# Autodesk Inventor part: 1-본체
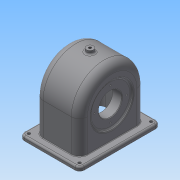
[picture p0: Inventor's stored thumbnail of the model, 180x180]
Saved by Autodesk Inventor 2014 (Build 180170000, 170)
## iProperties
Created: 2016-01
Part Number: 1-본체
Material: Generic
Document SubType Name: Modeling
Designer: Administrator
Density: 1 g/cm^3
Appearance: Default
Author: Administrator
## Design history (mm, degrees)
sketch "스케치1"
  geometry: L1 (-44, -70)-(44, -70); L2 (52, -62)-(52, 62); L3 (44, 70)-(-44, 70); L4 (-52, 62)-(-52, -62); L5 (-52, -70)-(52, 70); L6 (52, -70)-(-52, 70); A1 r 8 centre (-44, 62) between (-44, 70) and (-52, 62); A2 r 8 centre (44, 62) between (52, 62) and (44, 70); A3 r 8 centre (-44, -62) between (-52, -62) and (-44, -70); A4 r 8 centre (44, -62) between (44, -70) and (52, -62); 1 further point
  constraints: 12 end point, 8 point on circle, 8 point on line, 8 tangent, 4 centre point, 3 equal radius, 2 midpoint, 2 parallel, 1 horizontal, 1 perpendicular
  dimensions: "d0" = 104 distance of L5.end L6.end; "d1" = 140 distance of L6.start L5.end; "d2" = 8 radius of A1
extrude "돌출1" new body sketch "스케치1" distance "d3" = 7; taper "d4" = 0 deg
node "작업 평면1"
sketch "스케치3"
  geometry: L1 (-7, 124)-(-7, 0) reference; L2 (-64, 11)-(-7, 11); L3 (-64, 113)-(-7, 113); L4 (-64, 5)-(-7, 5); L5 (-64, 119)-(-7, 119); L6 (-7, 5)-(-7, 119); A1 r 57 centre (-64, 62) between (-64, 119) and (-64, 5); A2 r 51 centre (-64, 62) between (-64, 113) and (-64, 11); 1 further point
  constraints: 10 end point, 4 perpendicular, 4 point on circle, 4 point on line, 4 tangent, 2 centre point, 1 coincident, 1 collinear
  dimensions: "d6" = 57 radius of A1; "d7" = 64 distance of point (0, 62) A1.centre; "d8" = 0 vertical distance of A1.centre point (0, 62); "d12" = 102 diameter of A2
extrude "돌출3" join sketch "스케치3" stored distance "d15" = 77; taper "d16" = 0 deg
extrude "돌출4" cut sketch "스케치3" stored distance "d17" = 67; taper "d18" = 0 deg
node "작업 평면3"
sketch "스케치5"
  geometry: L1 (-38.5, 57)-(-38.5, -57) reference; L2 (38.5, -57)-(38.5, 57) reference; L3 (0, 0)-(67.019, 0); L4 (48.5, 0)-(48.5, 31); L5 (48.5, 31)-(38.5, 31); L6 (38.5, 31)-(38.5, 0)
  constraints: 8 end point, 3 perpendicular, 3 point on line, 1 midpoint
  dimensions: "d20" = 62 diameter of L5 L3; "d21" = 10 distance between parallel lines of L4 L2
revolve "회전1" sketch "스케치5" stored, may be unused: angle "d22" = 90 deg
sketch "스케치6"
  geometry: L1 (48.5, -31)-(48.5, 31) reference; L2 (-33.5, 51)-(-33.5, -51) reference; L3 (38.5, 57)-(-38.5, 57) reference; L4 (0, 0)-(-44.74, 0); L5 (-33.5, 39.747)-(-19.5, 28); L6 (-19.5, 28)-(-19.5, 0); L7 (-33.5, 39.747)-(-33.5, 0); L8 (-38.5, 57)-(-38.5, -57) reference; 1 further point
  constraints: 8 end point, 3 point on line, 1 coincident, 1 midpoint, 1 parallel, 1 perpendicular
  dimensions: "d26" = 33.5 distance from line of point (0, 0) L2 (derived); "d27" = 56 diameter of L5.end L4; "d28" = 50 deg angle of L6 L5; "d30" = 19 distance between parallel lines of L8 L6
revolve "회전2" sketch "스케치6" stored, may be unused: angle "d31" = 90 deg
sketch "스케치7"
  geometry: L1 (0, 0)-(57.526, 0); L2 (33.5, -51)-(33.5, 51) reference; L3 (33.5, 20)-(43.5, 20); L4 (33.5, 20)-(33.5, 0); L5 (-33.5, 39.747)-(-19.5, 28) reference; L6 (-19.5, -28)-(-19.5, 28) reference; L7 (0, 0)-(-45.884, 0); L8 (-19.5, 20)-(-35.5, 20); L9 (-35.5, 20)-(-35.5, 34.899); L10 (-38.5, 57)-(-38.5, -57) reference; L11 (-35.5, 34.899)-(-38.5, 37.416); L12 (-38.5, 37.416)-(-38.5, 0); L13 (-19.5, 20)-(-19.5, 0); L14 (-19.5, 0)-(-38.5, 0); L15 (33.5, 0)-(43.5, 0); L16 (48.5, -31)-(48.5, 31) reference; L17 (43.5, 20)-(48.5, 20); L18 (48.5, 20)-(48.5, 0); L19 (48.5, 0)-(43.5, 0)
  constraints: 28 end point, 6 point on line, 4 midpoint, 4 perpendicular, 3 collinear, 2 parallel, 1 horizontal
  dimensions: "d32" = 40 diameter of L3 L1; "d34" = 5 distance between parallel lines of L11 L5; "d35" = 40 diameter of L8 L7; "d36" = 3 distance between parallel lines of L9 L10
revolve "회전3" sketch "스케치7" stored, may be unused: angle "d37" = 90 deg
node "작업 평면4"
sketch "스케치8"
  geometry: C1 r 6 at (0, 0); 1 further point
  constraints: 1 centre point, 1 coincident
  dimensions: "d39" = 12 diameter of C1
extrude "돌출5" join sketch "스케치8" stored distance "d40" = 67; taper "d41" = 0 deg
hole "구멍1" diameter "d44" = 4.459; stored, may be unused: countersink angle "d48" = 90 deg, drill point angle "d50" = 118 deg; dims "d42" = 10, "d43" = 10, "d45" = 6, "d46" = 4, "d47" = 2, "d49" = 8
sketch "스케치9"
  geometry: C1 r 20 at (0, 0) reference; C2 r 31 at (0, 0) reference; A1 r 24 centre (0, 0) between (0, 24) and (-24, 0); 3 further points
  constraints: 4 point on circle, 2 horizontal alignment, 2 vertical alignment, 1 centre point, 1 coincident
  dimensions: "d51" = 48 diameter of A1
hole "구멍2" sketch "스케치9" at (0, 24), (-24, 0), (0, -24), (24, 0) diameter "d52" = 2.459; stored, may be unused: countersink angle "d56" = 90 deg, drill point angle "d58" = 118 deg; dims "d53" = 6, "d54" = 4, "d55" = 2, "d57" = 8
fillet "모깎기1" dims "d59" = 3
chamfer "모따기1" distance "d60" = 1; stored, may be unused: second distance "d61" = 2, angle "d62" = 45 deg
fillet "모깎기2" dims "d63" = 3
sketch "스케치10"
  geometry: C1 r 21 at (0, 0) reference; C2 r 33.5 at (0, 0) reference; A1 r 28 centre (0, 0) between (-28, 0) and (0, -28); 3 further points
  constraints: 4 point on circle, 2 horizontal alignment, 2 vertical alignment, 1 centre point, 1 coincident
  dimensions: "d64" = 56 diameter of A1
hole "구멍3" sketch "스케치10" at (-28, 0), (0, -28), (28, 0), (0, 28) diameter "d65" = 2.459; stored, may be unused: countersink angle "d69" = 90 deg, drill point angle "d71" = 118 deg; dims "d66" = 7, "d67" = 4, "d68" = 2, "d70" = 9
fillet "모깎기3" dims "d72" = 3, "d73" = 14
sketch "스케치12"
  geometry: L1 (-33.5, -51)-(33.5, -51); L2 (33.5, -51)-(33.5, 51); L3 (33.5, 51)-(-33.5, 51); L4 (-33.5, 51)-(-33.5, -51); L5 (-33.5, -51)-(33.5, 51); L6 (33.5, -51)-(-33.5, 51); 1 further point
  constraints: 12 end point, 2 midpoint, 2 parallel, 1 horizontal, 1 perpendicular
  dimensions: "d79" = 67 distance of L2.end L3.end; "d80" = 102 distance of L1.end L2.end
extrude "돌출7" cut sketch "스케치12" stored distance "d81" = 67; taper "d82" = 0 deg
sketch "스케치13"
  geometry: L1 (-19.5, 64)-(68.5, 64) reference; L2 (63, 0)-(63, 57) reference; 3 further points
  constraints: 1 coincident, 1 other
  dimensions: "d83" = 30 distance from line of L1 point (24.5, 34); "d84" = 38.5 distance from line of point (24.5, 34) L2
feature "엠보싱1" sketch "스케치13" dims "d0" = 104, "d1" = 140, "d2" = 8, "d6" = 57, "d7" = 64, "d8" = 0, "d12" = 102, "d85" = 0.5, "d86" = 0
hole "구멍4" diameter "d89" = 5; stored, may be unused: countersink angle "d93" = 90 deg, drill point angle "d95" = 118 deg; dims "d87" = 10, "d88" = 10, "d90" = 7, "d91" = 4, "d92" = 2, "d94" = 9
fillet "모깎기4" dims "d102" = 9, "d103" = 3
fillet "모깎기5" dims "d104" = 1
node "솔리드1"
pattern_linear "직사각형 패턴1" dims "d98" = 88, "d101" = 124
other parameters: "d38" = -127
